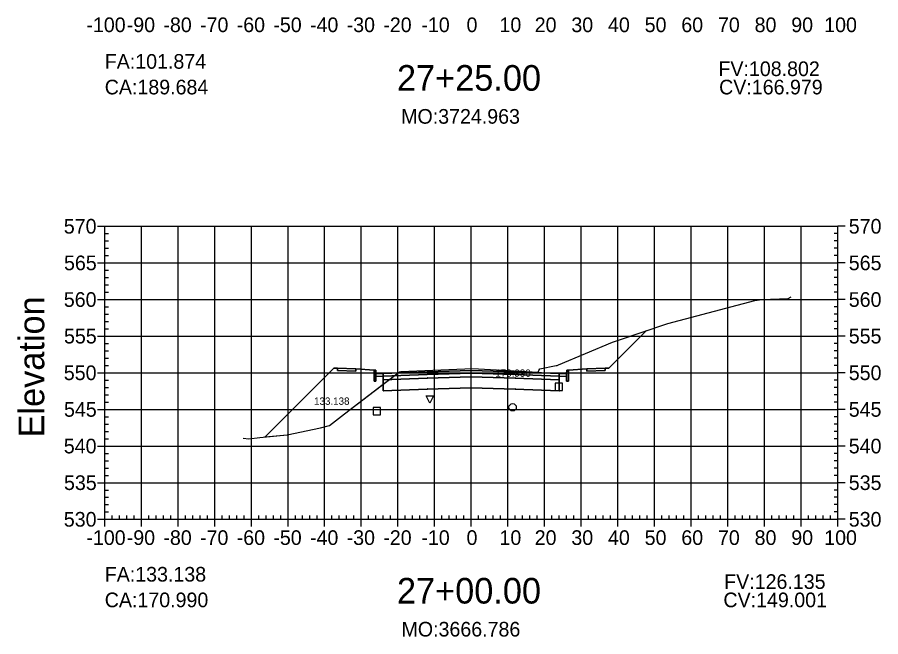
# Model space of a CAD drawing. Extents: x 704834 to 709892, y 372981 to 377533.
# Drawn here: x 706288 to 706523.6, y 372980.8 to 373149.9 of the extents above; entities that cross this region are included whole.
import ezdxf

# ---------------------------------------------------------------- set-up
doc = ezdxf.new("R2010")
doc.units = 0
for name, color, linetype in [('1', 7, 'Continuous'), ('10', 7, 'Continuous'), ('13', 7, 'Continuous'), ('14', 7, 'Continuous'), ('4', 7, 'Continuous'), ('57', 7, 'Continuous'), ('59', 7, 'Continuous'), ('60', 7, 'Continuous'), ('Default_Xsect', 7, 'Continuous'), ('Existing', 7, 'Continuous')]:
    doc.layers.add(name, color=color, linetype=linetype)

msp = doc.modelspace()

# ---------------------------------------------------------------- linework, layer by layer
for points in [[(706449.37, 373054.06), (706459.55, 373064.24)], [(706374.37, 373054.06), (706355.63, 373035.32)], [(706375.37, 373054.1), (706374.37, 373054.06)], [(706385.37, 373053.5), (706380.37, 373053.9)], [(706438.37, 373053.5), (706443.37, 373053.9)], [(706448.37, 373054.1), (706449.37, 373054.06)]]:
    msp.add_lwpolyline(points)
for points in [[(706380.37, 373053.9), (706375.37, 373054.1), (706375.37, 373053.43), (706380.37, 373053.23)], [(706443.37, 373053.23), (706448.37, 373053.43), (706448.37, 373054.1), (706443.37, 373053.9)], [(706385.87, 373052.5), (706385.79, 373053.5), (706385.37, 373053.5), (706385.37, 373050.5), (706385.87, 373050.5)], [(706387.87, 373052.58), (706385.87, 373052.5), (706385.87, 373051.83), (706387.87, 373051.91)], [(706411.87, 373052.75), (706423.87, 373052.39), (706435.87, 373051.91), (706435.87, 373052.58), (706423.87, 373053.06), (706411.87, 373053.42), (706399.87, 373053.06), (706387.87, 373052.58), (706387.87, 373051.91), (706399.87, 373052.39)], [(706411.87, 373051.75), (706423.87, 373051.39), (706435.87, 373050.91), (706435.87, 373051.91), (706423.87, 373052.39), (706411.87, 373052.75), (706399.87, 373052.39), (706387.87, 373051.91), (706387.87, 373050.91), (706399.87, 373051.39)], [(706411.87, 373048.75), (706423.87, 373048.39), (706435.87, 373047.91), (706435.87, 373050.91), (706423.87, 373051.39), (706411.87, 373051.75), (706399.87, 373051.39), (706387.87, 373050.91), (706387.87, 373047.91), (706399.87, 373048.39)], [(706399.82, 373051.34), (706399.92, 373051.34), (706399.92, 373051.44), (706399.82, 373051.44)], [(706411.82, 373052.7), (706411.92, 373052.7), (706411.92, 373052.8), (706411.82, 373052.8)], [(706411.82, 373051.7), (706411.92, 373051.7), (706411.92, 373051.8), (706411.82, 373051.8)], [(706423.82, 373051.34), (706423.92, 373051.34), (706423.92, 373051.44), (706423.82, 373051.44)], [(706435.87, 373051.91), (706437.87, 373051.83), (706437.87, 373052.5), (706435.87, 373052.58)], [(706437.87, 373050.5), (706438.37, 373050.5), (706438.37, 373053.5), (706437.96, 373053.5), (706437.87, 373052.5)], [(706387.82, 373050.86), (706387.92, 373050.86), (706387.92, 373050.96), (706387.82, 373050.96)], [(706435.82, 373050.86), (706435.92, 373050.86), (706435.92, 373050.96), (706435.82, 373050.96)], [(706387.82, 373047.86), (706387.92, 373047.86), (706387.92, 373047.96), (706387.82, 373047.96)], [(706399.82, 373048.34), (706399.92, 373048.34), (706399.92, 373048.44), (706399.82, 373048.44)], [(706411.82, 373048.7), (706411.92, 373048.7), (706411.92, 373048.8), (706411.82, 373048.8)], [(706423.82, 373048.34), (706423.92, 373048.34), (706423.92, 373048.44), (706423.82, 373048.44)], [(706435.82, 373047.86), (706435.92, 373047.86), (706435.92, 373047.96), (706435.82, 373047.96)]]:
    msp.add_lwpolyline(points, close=True)
at = {"layer": '1'}
for points in [[(706387.87, 373049.68), (706392.31, 373053.07), (706392.63, 373053.21), (706410.09, 373053.94), (706411.63, 373054.02), (706413.81, 373053.88), (706430.09, 373053.03), (706430.29, 373053.41), (706430.57, 373053.91), (706435.04, 373054.84), (706435.29, 373054.84), (706435.69, 373054.96), (706450.38, 373061.19), (706451.24, 373061.41), (706459.55, 373064.24), (706449.37, 373054.06), (706448.37, 373054.1), (706448.37, 373053.43), (706443.37, 373053.23), (706443.37, 373053.9), (706438.37, 373053.5), (706438.37, 373050.5), (706437.87, 373050.5), (706437.87, 373051.83), (706435.87, 373051.91), (706435.87, 373050.91), (706435.87, 373047.91), (706423.87, 373048.39), (706411.87, 373048.75), (706399.87, 373048.39), (706387.87, 373047.91)], [(706355.63, 373035.32), (706361.62, 373035.87), (706370.71, 373037.78), (706373.19, 373038.4), (706377.26, 373041.59), (706387.87, 373049.68), (706387.87, 373050.91), (706387.87, 373051.91), (706385.87, 373051.83), (706385.87, 373050.5), (706385.37, 373050.5), (706385.37, 373053.5), (706380.37, 373053.9), (706380.37, 373053.23), (706375.37, 373053.43), (706375.37, 373054.1), (706374.37, 373054.06)], [(706400.54, 373044.54), (706399.54, 373046.54), (706401.54, 373046.54)]]:
    msp.add_lwpolyline(points, close=True, dxfattribs=at)
at = {"layer": '10'}
msp.add_lwpolyline([(706385.15, 373041.37), (706387.15, 373041.37), (706387.15, 373043.37), (706385.15, 373043.37)], close=True, dxfattribs=at)
at = {"layer": '13'}
msp.add_circle((706423.16, 373043.39), 1, dxfattribs=at)
at = {"layer": '14'}
for points in [[(706459.55, 373064.24), (706459.55, 373064.29), (706459.55, 373064.24), (706459.5, 373064.24), (706459.55, 373064.24), (706459.55, 373064.19), (706459.55, 373064.24), (706459.6, 373064.24)], [(706387.87, 373052.58), (706387.87, 373052.63), (706387.87, 373052.58), (706387.82, 373052.58), (706387.87, 373052.58), (706387.87, 373052.53), (706387.87, 373052.58), (706387.92, 373052.58)], [(706399.87, 373053.06), (706399.87, 373053.11), (706399.87, 373053.06), (706399.82, 373053.06), (706399.87, 373053.06), (706399.87, 373053.01), (706399.87, 373053.06), (706399.92, 373053.06)], [(706411.87, 373053.42), (706411.87, 373053.47), (706411.87, 373053.42), (706411.82, 373053.42), (706411.87, 373053.42), (706411.87, 373053.37), (706411.87, 373053.42), (706411.92, 373053.42)], [(706423.87, 373053.06), (706423.87, 373053.11), (706423.87, 373053.06), (706423.82, 373053.06), (706423.87, 373053.06), (706423.87, 373053.01), (706423.87, 373053.06), (706423.92, 373053.06)], [(706435.87, 373052.58), (706435.87, 373052.63), (706435.87, 373052.58), (706435.82, 373052.58), (706435.87, 373052.58), (706435.87, 373052.53), (706435.87, 373052.58), (706435.92, 373052.58)], [(706355.63, 373035.32), (706355.63, 373035.37), (706355.63, 373035.32), (706355.58, 373035.32), (706355.63, 373035.32), (706355.63, 373035.27), (706355.63, 373035.32), (706355.68, 373035.32)]]:
    msp.add_lwpolyline(points, dxfattribs=at)
at = {"layer": '4'}
msp.add_lwpolyline([(706434.79, 373048.01), (706436.79, 373048.01), (706436.79, 373050.01), (706434.79, 373050.01)], close=True, dxfattribs=at)
at = {"layer": '57'}
for p, q in [((706309.87, 373092.82), (706311.87, 373092.82)), ((706311.87, 373092.82), (706511.87, 373092.82)), ((706311.87, 373012.82), (706311.87, 373092.82)), ((706311.87, 373012.82), (706311.87, 373092.82)), ((706321.87, 373012.82), (706321.87, 373092.82)), ((706331.87, 373012.82), (706331.87, 373092.82)), ((706341.87, 373012.82), (706341.87, 373092.82)), ((706351.87, 373012.82), (706351.87, 373092.82)), ((706361.87, 373012.82), (706361.87, 373092.82)), ((706371.87, 373012.82), (706371.87, 373092.82)), ((706381.87, 373012.82), (706381.87, 373092.82)), ((706391.87, 373012.82), (706391.87, 373092.82)), ((706401.87, 373012.82), (706401.87, 373092.82)), ((706411.87, 373012.82), (706411.87, 373092.82)), ((706421.87, 373012.82), (706421.87, 373092.82)), ((706431.87, 373012.82), (706431.87, 373092.82)), ((706441.87, 373012.82), (706441.87, 373092.82)), ((706451.87, 373012.82), (706451.87, 373092.82)), ((706461.87, 373012.82), (706461.87, 373092.82)), ((706471.87, 373012.82), (706471.87, 373092.82)), ((706481.87, 373012.82), (706481.87, 373092.82)), ((706491.87, 373012.82), (706491.87, 373092.82)), ((706501.87, 373012.82), (706501.87, 373092.82)), ((706511.87, 373012.82), (706511.87, 373092.82)), ((706511.87, 373012.82), (706511.87, 373092.82)), ((706513.87, 373092.82), (706511.87, 373092.82)), ((706311.87, 373090.82), (706312.87, 373090.82)), ((706511.87, 373090.82), (706510.87, 373090.82)), ((706311.87, 373088.82), (706312.87, 373088.82)), ((706311.87, 373086.82), (706312.87, 373086.82)), ((706511.87, 373088.82), (706510.87, 373088.82)), ((706511.87, 373086.82), (706510.87, 373086.82)), ((706311.87, 373084.82), (706312.87, 373084.82)), ((706511.87, 373084.82), (706510.87, 373084.82)), ((706309.87, 373082.82), (706311.87, 373082.82)), ((706311.87, 373082.82), (706511.87, 373082.82)), ((706513.87, 373082.82), (706511.87, 373082.82)), ((706311.87, 373080.82), (706312.87, 373080.82)), ((706511.87, 373080.82), (706510.87, 373080.82)), ((706311.87, 373078.82), (706312.87, 373078.82)), ((706511.87, 373078.82), (706510.87, 373078.82)), ((706311.87, 373076.82), (706312.87, 373076.82)), ((706511.87, 373076.82), (706510.87, 373076.82)), ((706309.87, 373072.82), (706311.87, 373072.82)), ((706311.87, 373074.82), (706312.87, 373074.82)), ((706311.87, 373072.82), (706511.87, 373072.82)), ((706511.87, 373074.82), (706510.87, 373074.82)), ((706513.87, 373072.82), (706511.87, 373072.82)), ((706311.87, 373070.82), (706312.87, 373070.82)), ((706511.87, 373070.82), (706510.87, 373070.82)), ((706311.87, 373068.82), (706312.87, 373068.82)), ((706511.87, 373068.82), (706510.87, 373068.82)), ((706311.87, 373066.82), (706312.87, 373066.82)), ((706511.87, 373066.82), (706510.87, 373066.82)), ((706311.87, 373064.82), (706312.87, 373064.82)), ((706511.87, 373064.82), (706510.87, 373064.82)), ((706309.87, 373062.82), (706311.87, 373062.82)), ((706311.87, 373062.82), (706511.87, 373062.82)), ((706513.87, 373062.82), (706511.87, 373062.82)), ((706311.87, 373060.82), (706312.87, 373060.82)), ((706311.87, 373058.82), (706312.87, 373058.82)), ((706511.87, 373060.82), (706510.87, 373060.82)), ((706511.87, 373058.82), (706510.87, 373058.82)), ((706311.87, 373056.82), (706312.87, 373056.82)), ((706511.87, 373056.82), (706510.87, 373056.82)), ((706311.87, 373054.82), (706312.87, 373054.82)), ((706511.87, 373054.82), (706510.87, 373054.82)), ((706309.87, 373052.82), (706311.87, 373052.82)), ((706311.87, 373052.82), (706511.87, 373052.82)), ((706513.87, 373052.82), (706511.87, 373052.82)), ((706311.87, 373050.82), (706312.87, 373050.82)), ((706511.87, 373050.82), (706510.87, 373050.82)), ((706311.87, 373048.82), (706312.87, 373048.82)), ((706311.87, 373046.82), (706312.87, 373046.82)), ((706511.87, 373048.82), (706510.87, 373048.82)), ((706511.87, 373046.82), (706510.87, 373046.82)), ((706311.87, 373044.82), (706312.87, 373044.82)), ((706511.87, 373044.82), (706510.87, 373044.82)), ((706309.87, 373042.82), (706311.87, 373042.82)), ((706311.87, 373042.82), (706511.87, 373042.82)), ((706513.87, 373042.82), (706511.87, 373042.82)), ((706311.87, 373040.82), (706312.87, 373040.82)), ((706511.87, 373040.82), (706510.87, 373040.82)), ((706311.87, 373038.82), (706312.87, 373038.82)), ((706511.87, 373038.82), (706510.87, 373038.82)), ((706311.87, 373036.82), (706312.87, 373036.82)), ((706511.87, 373036.82), (706510.87, 373036.82)), ((706309.87, 373032.82), (706311.87, 373032.82)), ((706311.87, 373034.82), (706312.87, 373034.82)), ((706311.87, 373032.82), (706511.87, 373032.82)), ((706511.87, 373034.82), (706510.87, 373034.82)), ((706513.87, 373032.82), (706511.87, 373032.82)), ((706311.87, 373030.82), (706312.87, 373030.82)), ((706511.87, 373030.82), (706510.87, 373030.82)), ((706311.87, 373028.82), (706312.87, 373028.82)), ((706511.87, 373028.82), (706510.87, 373028.82)), ((706311.87, 373026.82), (706312.87, 373026.82)), ((706511.87, 373026.82), (706510.87, 373026.82)), ((706311.87, 373024.82), (706312.87, 373024.82)), ((706511.87, 373024.82), (706510.87, 373024.82)), ((706309.87, 373022.82), (706311.87, 373022.82)), ((706311.87, 373022.82), (706511.87, 373022.82)), ((706311.87, 373020.82), (706312.87, 373020.82)), ((706511.87, 373020.82), (706510.87, 373020.82)), ((706513.87, 373022.82), (706511.87, 373022.82)), ((706311.87, 373018.82), (706312.87, 373018.82)), ((706511.87, 373018.82), (706510.87, 373018.82)), ((706311.87, 373016.82), (706312.87, 373016.82)), ((706511.87, 373016.82), (706510.87, 373016.82)), ((706311.87, 373014.82), (706312.87, 373014.82)), ((706313.87, 373012.82), (706313.87, 373013.82)), ((706315.87, 373012.82), (706315.87, 373013.82)), ((706317.87, 373012.82), (706317.87, 373013.82)), ((706319.87, 373012.82), (706319.87, 373013.82)), ((706323.87, 373012.82), (706323.87, 373013.82)), ((706325.87, 373012.82), (706325.87, 373013.82)), ((706327.87, 373012.82), (706327.87, 373013.82)), ((706329.87, 373012.82), (706329.87, 373013.82)), ((706333.87, 373012.82), (706333.87, 373013.82)), ((706335.87, 373012.82), (706335.87, 373013.82)), ((706337.87, 373012.82), (706337.87, 373013.82)), ((706339.87, 373012.82), (706339.87, 373013.82)), ((706343.87, 373012.82), (706343.87, 373013.82)), ((706345.87, 373012.82), (706345.87, 373013.82)), ((706347.87, 373012.82), (706347.87, 373013.82)), ((706349.87, 373012.82), (706349.87, 373013.82)), ((706353.87, 373012.82), (706353.87, 373013.82)), ((706355.87, 373012.82), (706355.87, 373013.82)), ((706357.87, 373012.82), (706357.87, 373013.82)), ((706359.87, 373012.82), (706359.87, 373013.82)), ((706363.87, 373012.82), (706363.87, 373013.82)), ((706365.87, 373012.82), (706365.87, 373013.82)), ((706367.87, 373012.82), (706367.87, 373013.82)), ((706369.87, 373012.82), (706369.87, 373013.82)), ((706373.87, 373012.82), (706373.87, 373013.82)), ((706375.87, 373012.82), (706375.87, 373013.82)), ((706377.87, 373012.82), (706377.87, 373013.82)), ((706379.87, 373012.82), (706379.87, 373013.82)), ((706383.87, 373012.82), (706383.87, 373013.82)), ((706385.87, 373012.82), (706385.87, 373013.82)), ((706387.87, 373012.82), (706387.87, 373013.82)), ((706389.87, 373012.82), (706389.87, 373013.82)), ((706393.87, 373012.82), (706393.87, 373013.82)), ((706395.87, 373012.82), (706395.87, 373013.82)), ((706397.87, 373012.82), (706397.87, 373013.82)), ((706399.87, 373012.82), (706399.87, 373013.82)), ((706403.87, 373012.82), (706403.87, 373013.82)), ((706405.87, 373012.82), (706405.87, 373013.82)), ((706407.87, 373012.82), (706407.87, 373013.82)), ((706409.87, 373012.82), (706409.87, 373013.82)), ((706413.87, 373012.82), (706413.87, 373013.82)), ((706415.87, 373012.82), (706415.87, 373013.82)), ((706417.87, 373012.82), (706417.87, 373013.82)), ((706419.87, 373012.82), (706419.87, 373013.82)), ((706423.87, 373012.82), (706423.87, 373013.82)), ((706425.87, 373012.82), (706425.87, 373013.82)), ((706427.87, 373012.82), (706427.87, 373013.82)), ((706429.87, 373012.82), (706429.87, 373013.82)), ((706433.87, 373012.82), (706433.87, 373013.82)), ((706435.87, 373012.82), (706435.87, 373013.82)), ((706437.87, 373012.82), (706437.87, 373013.82)), ((706439.87, 373012.82), (706439.87, 373013.82)), ((706443.87, 373012.82), (706443.87, 373013.82)), ((706445.87, 373012.82), (706445.87, 373013.82)), ((706447.87, 373012.82), (706447.87, 373013.82)), ((706449.87, 373012.82), (706449.87, 373013.82)), ((706453.87, 373012.82), (706453.87, 373013.82)), ((706455.87, 373012.82), (706455.87, 373013.82)), ((706457.87, 373012.82), (706457.87, 373013.82)), ((706459.87, 373012.82), (706459.87, 373013.82)), ((706463.87, 373012.82), (706463.87, 373013.82)), ((706465.87, 373012.82), (706465.87, 373013.82)), ((706467.87, 373012.82), (706467.87, 373013.82)), ((706469.87, 373012.82), (706469.87, 373013.82)), ((706473.87, 373012.82), (706473.87, 373013.82)), ((706475.87, 373012.82), (706475.87, 373013.82)), ((706477.87, 373012.82), (706477.87, 373013.82)), ((706479.87, 373012.82), (706479.87, 373013.82)), ((706483.87, 373012.82), (706483.87, 373013.82)), ((706485.87, 373012.82), (706485.87, 373013.82)), ((706487.87, 373012.82), (706487.87, 373013.82)), ((706489.87, 373012.82), (706489.87, 373013.82)), ((706493.87, 373012.82), (706493.87, 373013.82)), ((706495.87, 373012.82), (706495.87, 373013.82)), ((706497.87, 373012.82), (706497.87, 373013.82)), ((706499.87, 373012.82), (706499.87, 373013.82)), ((706503.87, 373012.82), (706503.87, 373013.82)), ((706505.87, 373012.82), (706505.87, 373013.82)), ((706507.87, 373012.82), (706507.87, 373013.82)), ((706509.87, 373012.82), (706509.87, 373013.82)), ((706511.87, 373014.82), (706510.87, 373014.82)), ((706309.87, 373012.82), (706311.87, 373012.82)), ((706311.87, 373012.82), (706511.87, 373012.82)), ((706311.87, 373012.82), (706511.87, 373012.82)), ((706311.87, 373010.82), (706311.87, 373012.82)), ((706321.87, 373010.82), (706321.87, 373012.82)), ((706331.87, 373010.82), (706331.87, 373012.82)), ((706341.87, 373010.82), (706341.87, 373012.82)), ((706351.87, 373010.82), (706351.87, 373012.82)), ((706361.87, 373010.82), (706361.87, 373012.82)), ((706371.87, 373010.82), (706371.87, 373012.82)), ((706381.87, 373010.82), (706381.87, 373012.82)), ((706391.87, 373010.82), (706391.87, 373012.82)), ((706401.87, 373010.82), (706401.87, 373012.82)), ((706411.87, 373010.82), (706411.87, 373012.82)), ((706421.87, 373010.82), (706421.87, 373012.82)), ((706431.87, 373010.82), (706431.87, 373012.82)), ((706441.87, 373010.82), (706441.87, 373012.82)), ((706451.87, 373010.82), (706451.87, 373012.82)), ((706461.87, 373010.82), (706461.87, 373012.82)), ((706471.87, 373010.82), (706471.87, 373012.82)), ((706481.87, 373010.82), (706481.87, 373012.82)), ((706491.87, 373010.82), (706491.87, 373012.82)), ((706501.87, 373010.82), (706501.87, 373012.82)), ((706511.87, 373010.82), (706511.87, 373012.82)), ((706513.87, 373012.82), (706511.87, 373012.82))]:
    msp.add_line(p, q, dxfattribs=at)
at = {"layer": 'Default_Xsect'}
msp.add_lwpolyline([(706355.63, 373035.32), (706374.37, 373054.06), (706375.37, 373054.1), (706380.37, 373053.9), (706385.37, 373053.5), (706385.79, 373053.5), (706385.87, 373052.5), (706387.87, 373052.58), (706399.87, 373053.06), (706411.87, 373053.42), (706423.87, 373053.06), (706435.87, 373052.58), (706437.87, 373052.5), (706437.96, 373053.5), (706438.37, 373053.5), (706443.37, 373053.9), (706448.37, 373054.1), (706449.37, 373054.06), (706459.55, 373064.24)], dxfattribs=at)
at = {"layer": 'Existing'}
msp.add_lwpolyline([(706349.65, 373034.96), (706351.2, 373034.8), (706354.2, 373035.19), (706361.62, 373035.87), (706370.71, 373037.78), (706373.19, 373038.4), (706377.26, 373041.59), (706392.31, 373053.07), (706392.63, 373053.21), (706410.09, 373053.94), (706411.63, 373054.02), (706413.81, 373053.88), (706430.09, 373053.03), (706430.29, 373053.41), (706430.57, 373053.91), (706435.04, 373054.84), (706435.29, 373054.84), (706435.69, 373054.96), (706450.38, 373061.19), (706451.24, 373061.41), (706465.48, 373066.26), (706489.26, 373072.57), (706491.14, 373072.8), (706498.3, 373073.11), (706499.11, 373073.58)], dxfattribs=at)

# ---------------------------------------------------------------- texts
for s, p in [('CA:189.684', (706311.87, 373128.82)), ('CV:166.979', (706479.5, 373128.82)), ('CA:170.990', (706311.87, 372988.82)), ('CV:149.001', (706480.67, 372988.82))]:
    msp.add_text(s, height=4).set_placement(p)
at = {"layer": '1'}
for s, p in [('27+25.00', (706391.6, 373129.82)), ('27+00.00', (706391.6, 372989.82))]:
    msp.add_text(s, height=7, dxfattribs=at).set_placement(p)
at = {"layer": '14'}
for p in [(706375.34, 373054.05), (706448.34, 373054.05), (706375.34, 373053.38), (706380.34, 373053.18), (706443.34, 373053.18), (706448.34, 373053.38)]:
    msp.add_text('+', height=0.1, dxfattribs=at).set_placement(p)
at = {"layer": '57'}
for s, p in [('-100', (706306.86, 373145.82)), ('-90', (706317.87, 373145.82)), ('-80', (706327.87, 373145.82)), ('-70', (706337.87, 373145.82)), ('-60', (706347.87, 373145.82)), ('-50', (706357.87, 373145.82)), ('-40', (706367.87, 373145.82)), ('-30', (706377.87, 373145.82)), ('-20', (706387.87, 373145.82)), ('-10', (706398.26, 373145.82)), ('0', (706410.58, 373145.82)), ('10', (706419.57, 373145.82)), ('20', (706429.18, 373145.82)), ('30', (706439.18, 373145.82)), ('40', (706449.18, 373145.82)), ('50', (706459.18, 373145.82)), ('60', (706469.18, 373145.82)), ('70', (706479.18, 373145.82)), ('80', (706489.18, 373145.82)), ('90', (706499.18, 373145.82)), ('100', (706508.17, 373145.82)), ('570', (706300.7, 373090.82)), ('570', (706514.87, 373090.82)), ('565', (706300.75, 373080.82)), ('565', (706514.87, 373080.82)), ('560', (706300.7, 373070.82)), ('560', (706514.87, 373070.82)), ('555', (706300.75, 373060.82)), ('555', (706514.87, 373060.82)), ('550', (706300.7, 373050.82)), ('550', (706514.87, 373050.82)), ('545', (706300.75, 373040.82)), ('545', (706514.87, 373040.82)), ('540', (706300.7, 373030.82)), ('540', (706514.87, 373030.82)), ('535', (706300.75, 373020.82)), ('535', (706514.87, 373020.82)), ('530', (706300.7, 373010.82)), ('530', (706514.87, 373010.82)), ('-100', (706306.86, 373005.82)), ('-90', (706317.87, 373005.82)), ('-80', (706327.87, 373005.82)), ('-70', (706337.87, 373005.82)), ('-60', (706347.87, 373005.82)), ('-50', (706357.87, 373005.82)), ('-40', (706367.87, 373005.82)), ('-30', (706377.87, 373005.82)), ('-20', (706387.87, 373005.82)), ('-10', (706398.26, 373005.82)), ('0', (706410.58, 373005.82)), ('10', (706419.57, 373005.82)), ('20', (706429.18, 373005.82)), ('30', (706439.18, 373005.82)), ('40', (706449.18, 373005.82)), ('50', (706459.18, 373005.82)), ('60', (706469.18, 373005.82)), ('70', (706479.18, 373005.82)), ('80', (706489.18, 373005.82)), ('90', (706499.18, 373005.82)), ('100', (706508.17, 373005.82))]:
    msp.add_text(s, height=4, dxfattribs=at).set_placement(p)
at = {"layer": '59'}
for s, height, p in [('FA:101.874', 4, (706311.87, 373135.82)), ('FV:108.802', 4, (706479.31, 373133.82)), ('MO:3724.963', 4, (706392.74, 373120.82)), ('170.990', 2, (706418.44, 373051.73)), ('133.138', 2, (706368.98, 373044.08)), ('FA:133.138', 4, (706311.87, 372995.82)), ('FV:126.135', 4, (706480.88, 372993.82)), ('MO:3666.786', 4, (706392.84, 372980.82))]:
    msp.add_text(s, height=height, dxfattribs=at).set_placement(p)
at = {"layer": '60'}
msp.add_text('Elevation', height=7, rotation=90, dxfattribs=at).set_placement((706295.37, 373035.18))

doc.saveas('drawing.dxf')
